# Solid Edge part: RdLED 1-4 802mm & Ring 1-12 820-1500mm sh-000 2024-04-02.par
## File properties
Author: jaroslaw.przewlocki
Template: iso metric part.par
Last saved by: jaroslaw.przewlocki
Revision: 1
Application: Solid Edge
Gęstość: 0,000 kg/m^3
Dokładność: 0,990
Username: jaroslaw.przewlocki
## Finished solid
Body 1: solid body, 24209 faces, 75598 edges, 52476 vertices, 8 separate solids.
  Faces by surface: plane 16620, cylinder 6299, torus 526, cone 440, spline 222, sphere 100, spun 2
  Edges by curve: line 52382, circle 13102, curve on surface 8730, spline 724, ellipse 660
Bounding box of the edges (mm; curved faces can reach further): 744.966 x 4.500 x 744.966, from (-749.962, -3.5004, 4.9963) to (-4.9957, 1, 749.9627).
Cylindrical faces by radius (mm): R0.1 x3264, R0.199 x10, R0.2 x2118, R0.2002 x20, R0.2169 x30, R0.25 x120, R0.3 x20, R0.3373 x30, R0.4 x80, R0.4006 x20, R0.4008 x20, R0.525 x20, R0.6 x120, R1 x70, R1.0894 x20, R1.0991 x40, R1.1 x140, R1.25 x8, R1.5342 x27, R1.5343 x9, R1.7452 x9, R1.7456 x27, R2.15 x55, R2.4981 x3, R2.4998 x3, R2.5 x6, R2.5011 x3, R401 x1, R411.0002 x3, R750 x3
Conical faces (half-angle, radius in mm at the cone's reference point): 0.3913 deg R1.0968 x20, 0.447 deg R1.0952 x20, 0.464 deg R1.0955 x20, 0.5 deg R0.5056 x40, 0.5 deg R1.0082 x40, 1 deg R0.5511 x20, 10 deg R0.2132 x20, 10 deg R0.4132 x20, 15.6748 deg R1.1041 x10, 15.6751 deg R1.1041 x10, 15.7937 deg R1.1267 x10, 15.7938 deg R1.1267 x10, 18.4844 deg R1.0657 x40, 18.9316 deg R0.5099 x20, 19.4335 deg R0.5111 x8, 19.4337 deg R0.5111 x12, 27.363 deg R0.6214 x20, 40.1747 deg R0.5201 x4, 40.1843 deg R0.5199 x4, 40.1968 deg R0.519 x6, 40.228 deg R0.5176 x6, 42.9179 deg R0.4919 x6, 42.9201 deg R0.4919 x4, 42.9331 deg R0.4916 x6, 42.9358 deg R0.4915 x4, 45 deg R0.575 x20, 45 deg R0.625 x40
Toroidal faces (ring radius, tube radius in mm): R0.0958 r0.3997 x40, R0.1 r0.2 x10, R0.1075 r0.4 x20, R0.1101 r0.4001 x20, R0.1216 r0.4 x20, R0.1234 r0.4 x20, R0.1634 r0.2287 x10, R0.1641 r0.2287 x10, R0.3286 r0.2001 x8, R0.3322 r0.2 x10, R0.3702 r0.4 x20, R0.3818 r0.2 x20, R0.4163 r0.3984 x20, R0.4824 r0.2001 x10, R0.4952 r0.2 x10, R0.6008 r0.3968 x12, R0.6009 r0.3968 x8, R0.6009 r0.3969 x20, R0.6227 r0.2 x8, R0.6235 r0.2 x10, R0.8 r0.2 x40, R0.8522 r0.3 x20, R0.9002 r0.2 x10, R0.9018 r0.2 x10, R0.9181 r0.2227 x20, R0.9197 r0.223 x10, R0.9199 r0.223 x10, R0.9663 r0.2263 x10, R0.9665 r0.2263 x10, R1.3 r0.2 x20, R1.327 r1.1 x20, R1.3271 r1.1 x20, R1.8741 r0.2175 x10, R1.8987 r0.2 x10
Spherical faces by radius (mm): R0.2 x80, R0.6 x20
Planar faces by outward normal: +x 80, +y 498, +z 68, -x 60, -y 2944, -z 80, oblique 12890
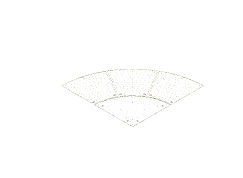
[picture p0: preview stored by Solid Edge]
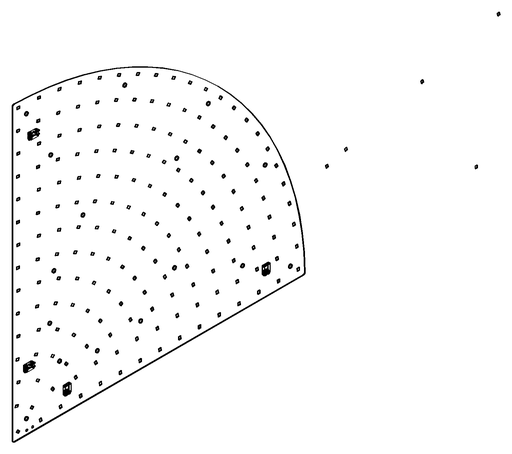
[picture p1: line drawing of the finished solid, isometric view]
